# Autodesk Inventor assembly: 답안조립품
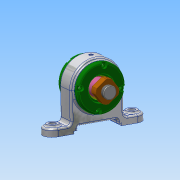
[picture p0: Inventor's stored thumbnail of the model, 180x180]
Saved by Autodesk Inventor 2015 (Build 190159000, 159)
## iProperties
Created: 2019-05
Part Number: 답안조립품
Document SubType Name: Assembly
Designer: user
Author: user
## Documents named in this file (7)
- C:\Users\user\Desktop\490504V1005\답안조립품.iam
- C:\Users\user\Desktop\490504V1005\축.ipt
- C:\Users\user\Desktop\490504V1005\앵귤러 볼 베어링 7205.ipt
- C:\Users\user\Desktop\490504V1005\칼라.ipt
- C:\Users\user\Desktop\490504V1005\커버.ipt
- C:\Users\user\Desktop\490504V1005\본체.ipt
- C:\Users\user\Desktop\490504V1005\베어링너트.ipt
